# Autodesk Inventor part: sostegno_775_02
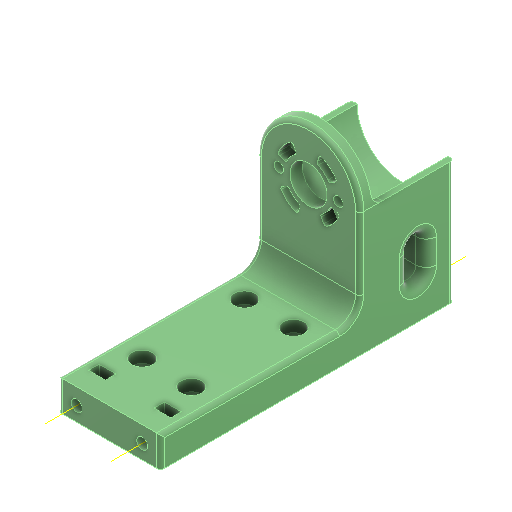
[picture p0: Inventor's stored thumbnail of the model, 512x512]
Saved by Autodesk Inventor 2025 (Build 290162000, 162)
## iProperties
Created: 2025-04
Part Number: sostegno_775_02
Material: Generico
Document SubType Name: Modeling
Designer: R5800u
Density: 1 g/cm^3
Appearance: Liscia - Verde foresta scuro
Author: R5800u
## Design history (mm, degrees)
sketch "Schizzo1"
  geometry: L1 (-25, 0)-(25, 0); L2 (25, 0)-(25, -60); L3 (25, -60)-(-25, -60); L4 (-25, -60)-(-25, 0); C1 r 9 at (0, 0); A1 r 25 centre (0, 0) between (-25, 0) and (25, 0); 1 further point
  constraints: 8 end point, 2 centre point, 2 coincident, 2 parallel, 2 point on circle, 1 horizontal, 1 perpendicular
  dimensions: "d0" = 50 diameter of A1; "d1" = 18 diameter of C1; "d4" = 60 distance of L1.end L2.end
extrude "Estrusione1" new body sketch "Schizzo1" distance "d2" = 6; taper "d3" = 0 deg
sketch "Schizzo2"
  geometry: C1 r 2.021 at (14.5, 0) reference; C2 r 1.621 at (-14.5, 0) reference; 1 further point
hole "Foro1" sketch "Schizzo2" at (14.5, 0), (-14.5, 0) diameter "d5" = 4.5; stored, may be unused: countersink angle "d9" = 90 deg, drill point angle "d11" = 118 deg; dims "d6" = 6, "d7" = 9.4, "d8" = 2, "d10" = 8
sketch "Schizzo3"
  geometry: L1 (4.262, 11.709)-(5.119, 14.064) reference; L2 (12.961, 7.483)-(10.791, 6.23) reference; A1 r 16 centre (0, 0) between (13.292, 8.906) and (6.462, 14.637) reference; A2 r 1 centre (6.059, 13.722) between (6.462, 14.637) and (5.119, 14.064) reference; A3 r 1 centre (5.201, 11.366) between (4.262, 11.709) and (4.785, 10.457) reference; A4 r 11.5 centre (0, 0) between (9.467, 6.528) and (4.785, 10.457) reference; A5 r 1 centre (10.291, 7.096) between (9.467, 6.528) and (10.791, 6.23) reference; A6 r 1 centre (12.461, 8.349) between (12.961, 7.483) and (13.292, 8.906) reference; 1 further point
extrude "Estrusione2" cut sketch "Schizzo3" distance "d12" = 10; taper "d13" = 0 deg
pattern_circular "Serie circolare1" dims angle "d15" = 360 deg
sketch "Schizzo4" dims "d17" = 44.5
  geometry: L1 (25, 0)-(25, -60) reference; L2 (-25, -60)-(-25, 0) reference; L3 (-14.064, -5.119)-(-11.709, -4.262) reference; L4 (-6.23, -10.791)-(-7.483, -12.961) reference; L5 (5.119, -14.064)-(4.262, -11.709) reference; L6 (10.791, -6.23)-(12.961, -7.483) reference; L7 (14.064, 5.119)-(11.709, 4.262) reference; L8 (6.23, 10.791)-(7.483, 12.961) reference; L9 (-5.119, 14.064)-(-4.262, 11.709) reference; L10 (-10.791, 6.23)-(-12.961, 7.483) reference; L11 (-25, -60)-(-25, 0) reference; L12 (25, -60)-(-25, -60) reference; L13 (25, 0)-(25, -60) reference; L14 (-25, 0)-(25, 0); C1 r 30 at (0, 0); C2 r 2.25 at (14.5, 0) reference; C3 r 2.25 at (-14.5, 0) reference; C4 r 9 at (0, 0) reference; A1 r 1 centre (-13.722, -6.059) between (-14.064, -5.119) and (-14.637, -6.462) reference; A2 r 1 centre (-11.366, -5.201) between (-10.457, -4.785) and (-11.709, -4.262) reference; A3 r 11.5 centre (0, 0) between (-10.457, -4.785) and (-6.528, -9.467) reference; A4 r 1 centre (-7.096, -10.291) between (-6.23, -10.791) and (-6.528, -9.467) reference; A5 r 1 centre (-8.349, -12.461) between (-8.906, -13.292) and (-7.483, -12.961) reference; A6 r 16 centre (0, 0) between (-14.637, -6.462) and (-8.906, -13.292) reference; A7 r 1 centre (6.059, -13.722) between (5.119, -14.064) and (6.462, -14.637) reference; A8 r 1 centre (5.201, -11.366) between (4.785, -10.457) and (4.262, -11.709) reference; A9 r 11.5 centre (0, 0) between (4.785, -10.457) and (9.467, -6.528) reference; A10 r 1 centre (10.291, -7.096) between (10.791, -6.23) and (9.467, -6.528) reference; A11 r 1 centre (12.461, -8.349) between (13.292, -8.906) and (12.961, -7.483) reference; A12 r 16 centre (0, 0) between (6.462, -14.637) and (13.292, -8.906) reference; A13 r 1 centre (13.722, 6.059) between (14.064, 5.119) and (14.637, 6.462) reference; A14 r 1 centre (11.366, 5.201) between (10.457, 4.785) and (11.709, 4.262) reference; A15 r 11.5 centre (0, 0) between (10.457, 4.785) and (6.528, 9.467) reference; A16 r 1 centre (7.096, 10.291) between (6.23, 10.791) and (6.528, 9.467) reference; A17 r 1 centre (8.349, 12.461) between (8.906, 13.292) and (7.483, 12.961) reference; A18 r 16 centre (0, 0) between (14.637, 6.462) and (8.906, 13.292) reference; A19 r 1 centre (-6.059, 13.722) between (-5.119, 14.064) and (-6.462, 14.637) reference; A20 r 1 centre (-5.201, 11.366) between (-4.785, 10.457) and (-4.262, 11.709) reference; A21 r 11.5 centre (0, 0) between (-4.785, 10.457) and (-9.467, 6.528) reference; A22 r 1 centre (-10.291, 7.096) between (-10.791, 6.23) and (-9.467, 6.528) reference; A23 r 1 centre (-12.461, 8.349) between (-13.292, 8.906) and (-12.961, 7.483) reference; A24 r 16 centre (0, 0) between (-6.462, 14.637) and (-13.292, 8.906) reference; A25 r 25 centre (0, 0) between (25, 0) and (-25, 0) reference; A26 r 25 centre (0, 0) between (25, 0) and (-25, 0) reference; 11 further points
  constraints: 2 coincident, 2 end point, 1 centre point, 1 horizontal, 2 other
  dimensions: "d18" = 60 diameter of C1
extrude "Estrusione3" join sketch "Schizzo4" distance "d19" = 40; taper "d20" = 0 deg
sketch "Schizzo9"
  geometry: L1 (-25, 0)-(-25, -60) reference; L2 (25, -60)-(25, 0) reference; L3 (-25, -60)-(25, -60); L4 (25, -60)-(25, -45); L5 (25, -45)-(-25, -45); L6 (-25, -45)-(-25, -60); 3 further points
  constraints: 8 end point, 2 parallel, 1 horizontal, 1 perpendicular, 1 point on line
  dimensions: "d46" = 15 distance of L4.end L3.end
node "Piano di lavoro1"
extrude "Estrusione7" join sketch "Schizzo9" stored distance "d47" = 40; taper "d48" = 0 deg
fillet "Raccordo3" dims "d49" = 10
sketch "Schizzo10"
  geometry: C1 r 2.5 at (9, 7) reference; C2 r 2.5 at (41, 7) reference; 1 further point
hole "Foro3" sketch "Schizzo10" at (41, 7), (9, 7) diameter "d50" = 5.23; stored, may be unused: countersink angle "d54" = 90 deg, drill point angle "d56" = 0 deg; dims "d51" = 6, "d52" = 4, "d53" = 2, "d55" = 20
fillet "Raccordo4" dims "d60" = 2
sketch "Schizzo12"
  geometry: L1 (11, -9.25)-(35, -9.25); L2 (35, -9.25)-(35, -59.25); L3 (35, -59.25)-(11, -59.25); L4 (11, -59.25)-(11, -9.25); L5 (11, -9.25)-(35, -59.25); L6 (35, -9.25)-(11, -59.25); L7 (0, -87.25)-(46, -87.25) reference; L8 (23, -87.25)-(23, 84.848); 8 further points
  constraints: 14 end point, 4 coincident, 3 midpoint, 2 parallel, 1 horizontal, 1 perpendicular, 1 point on line, 1 vertical
  dimensions: "d61" = 24 distance of L1.start L1.end; "d62" = 50 distance of L1.end L2.end; "d63" = 28 distance between parallel lines of L7 L3
hole "Foro4" sketch "Schizzo12" at (11, -9.25), (35, -9.25), (35, -59.25), (11, -59.25) diameter "d64" = 5.5; stored, may be unused: countersink angle "d68" = 90 deg, drill point angle "d70" = 0 deg; dims "d65" = 6, "d66" = 10, "d67" = 5.7, "d69" = 8
fillet "Raccordo5" dims "d71" = 1
node "Asse di lavoro1"
node "Asse di lavoro2"
node "Piano di lavoro2"
sketch "Schizzo13"
  geometry: L1 (8.984, 2.295)-(4.917, 4.661); L2 (4.917, 4.661)-(4.933, 9.367); L3 (4.933, 9.367)-(9.016, 11.705); L4 (9.016, 11.705)-(13.083, 9.339); L5 (13.083, 9.339)-(13.067, 4.633); L6 (13.067, 4.633)-(8.984, 2.295); L7 (50, 0)-(0, 0) reference; L8 (25, 0)-(25, 15); L9 (4.933, 9.367)-(4.933, 15); L10 (13.083, 9.339)-(13.083, 15); L11 (36.917, 9.339)-(36.917, 15); L12 (36.917, 9.339)-(36.933, 4.633); L13 (40.984, 11.705)-(36.917, 9.339); L14 (36.933, 4.633)-(41.016, 2.295); L15 (45.067, 9.367)-(40.984, 11.705); L16 (45.067, 9.367)-(45.067, 15); L17 (41.016, 2.295)-(45.083, 4.661); L18 (45.083, 4.661)-(45.067, 9.367); C1 r 2.615 at (9, 7) reference; C2 r 2.615 at (41, 7); 15 further points
  constraints: 34 end point, 10 symmetric about line, 2 coincident, 2 vertical, 1 centre point, 1 midpoint, 22 other
  dimensions: "d73" = 8.15 distance between parallel lines of L1 L4
extrude "Estrusione9" cut sketch "Schizzo13" distance "d74" = 5; taper "d75" = 0 deg
fillet "Raccordo6" dims "d81" = 5
sketch "Schizzo15"
  geometry: L1 (-15.5, 31.633)-(-15.5, 19.633); L2 (-33, 60)-(2, 60) reference; L3 (-19.5, 31.633)-(-19.5, 19.633); L4 (-11.5, 19.633)-(-11.5, 31.633); A1 r 4 centre (-15.5, 31.633) between (-11.5, 31.633) and (-19.5, 31.633); A2 r 4 centre (-15.5, 19.633) between (-19.5, 19.633) and (-11.5, 19.633); 2 further points
  constraints: 8 end point, 4 point on circle, 4 tangent, 2 centre point, 1 midpoint, 1 parallel, 1 perpendicular
  dimensions: "d82" = 6 distance of point (-15.5, 25.633) L1.end; "d83" = 8 diameter of A2
extrude "Estrusione11" cut sketch "Schizzo15" extent not by distance; stored distance "d84" = 0; taper "d85" = 0 deg
fillet "Raccordo7" dims "d86" = 5
node "Solido1"
node "Riferimento1"
node "Riferimento2"
node "Riferimento3"
node "Riferimento4"
node "Riferimento5"
node "Riferimento6"
node "Riferimento7"
node "Riferimento8"
node "Riferimento9"
node "Riferimento10"
node "Linea chiusa proiettata2"
node "Riferimento13"
node "Riferimento14"
